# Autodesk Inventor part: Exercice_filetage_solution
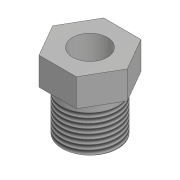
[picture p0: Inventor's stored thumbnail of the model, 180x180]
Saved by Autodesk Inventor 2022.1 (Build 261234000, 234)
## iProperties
Created: 2018-06
Part Number: Exercice_filetage_solution
Material: Générique
Document SubType Name: Modeling
Designer: Fabian Perrée
Density: 1 g/cm^3
Appearance: Gris clair
Mass: 1.44256 g
Surface Area: 12.9609 cm^2
Volume: 1.44256 cm^3
Author: Fabian Perrée
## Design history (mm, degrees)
sketch "Esquisse1"
  geometry: C1 r 6 at (0, 0); C2 r 3.75 at (0, 0); 1 further point
  constraints: 2 centre point, 2 coincident
  dimensions: "d0" = 12 diameter of C1; "d1" = 7.5 diameter of C2
extrude "Extrusion1" new body sketch "Esquisse1" distance "d2" = 16; taper "d3" = 0 deg
sketch "Esquisse2"
  geometry: L1 (4.041, -7)-(-4.041, -7); L2 (-4.041, -7)-(-8.083, 0); L3 (-8.083, 0)-(-4.041, 7); L4 (-4.041, 7)-(4.041, 7); L5 (4.041, 7)-(8.083, 0); L6 (8.083, 0)-(4.041, -7); C1 r 3.75 at (0, 0) reference; C2 r 6 at (0, 0) reference; 1 further point
  constraints: 12 end point, 1 coincident, 1 horizontal, 13 other
  dimensions: "d4" = 14 distance between parallel lines of L4 L1
extrude "Extrusion2" join sketch "Esquisse2" distance "d5" = 6; taper "d6" = 0 deg
feature "Filetage1" dims "d10" = 8, "d11" = 0
node "Solide1"
